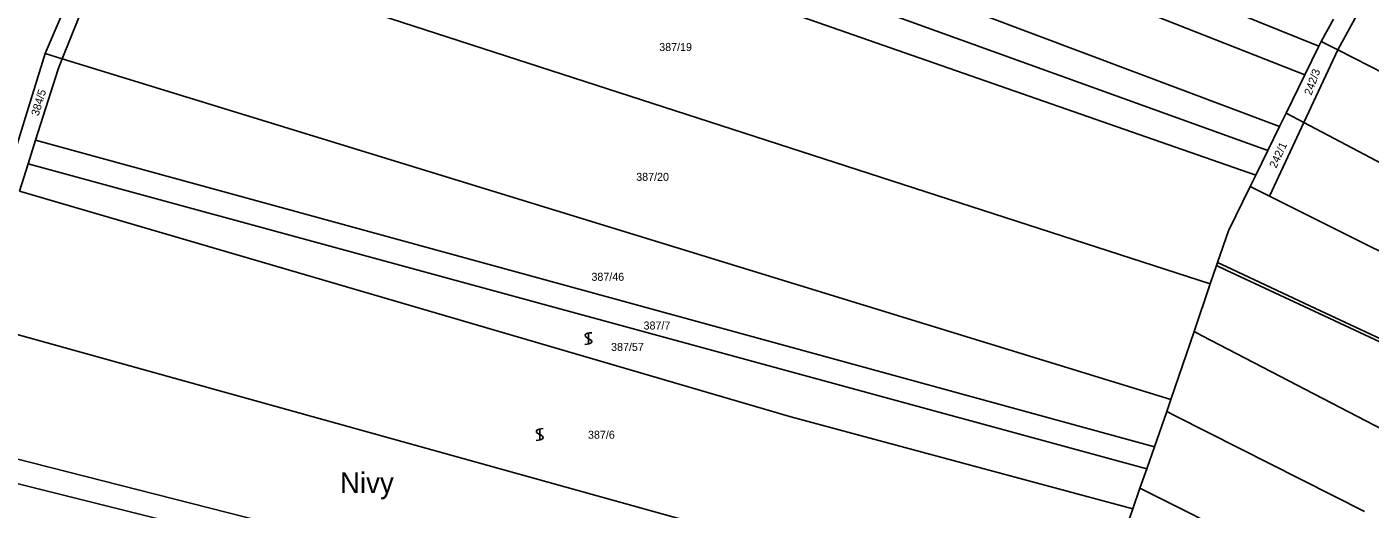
# Model space of a CAD drawing. Extents: x -580630 to -576196, y -1189024 to -1183567.
# Drawn here: x -580125.3 to -579840, y -1186458.9 to -1186356.5 of the extents above; entities that cross this region are included whole.
import ezdxf

# ---------------------------------------------------------------- set-up
doc = ezdxf.new("R2010")
doc.units = 0
for name, color, linetype in [('Vrstva 1', 7, 'Continuous'), ('Vrstva 15', 7, 'Continuous'), ('Vrstva 18', 7, 'Continuous'), ('Vrstva 25', 7, 'Continuous'), ('Vrstva 6', 7, 'Continuous')]:
    doc.layers.add(name, color=color, linetype=linetype)

msp = doc.modelspace()

# ---------------------------------------------------------------- linework, layer by layer
at = {"layer": 'Vrstva 1'}
for p, q in [((-580109.71, -1186334.74), (-580121.44, -1186362.13)), ((-580117.8, -1186363.25), (-580106.79, -1186335.69)), ((-579839.4, -1186347.64), (-579846.88, -1186361.39)), ((-579847.78, -1186354.85), (-579850.43, -1186359.58)), ((-579850.91, -1186360.56), (-579853.89, -1186366.65)), ((-579850.43, -1186359.58), (-579850.91, -1186360.56)), ((-580121.44, -1186362.13), (-580129.43, -1186388.07)), ((-580118.67, -1186365.44), (-580117.8, -1186363.25)), ((-579854.1, -1186376.82), (-579846.88, -1186361.39)), ((-580123.48, -1186380.56), (-580118.67, -1186365.44)), ((-579853.89, -1186366.65), (-579857.89, -1186374.82)), ((-579857.89, -1186374.82), (-579859.26, -1186377.63)), ((-579859.26, -1186377.63), (-579861.75, -1186382.72)), ((-579861.41, -1186392.44), (-579854.1, -1186376.82)), ((-580125.08, -1186385.6), (-580123.48, -1186380.56)), ((-579885.83, -1186445.67), (-580123.48, -1186380.56)), ((-579861.75, -1186382.72), (-579864.31, -1186387.96)), ((-580126.92, -1186391.37), (-580125.08, -1186385.6)), ((-579887.47, -1186450.37), (-580125.08, -1186385.6)), ((-579864.31, -1186387.96), (-579865.5, -1186390.4)), ((-579870.14, -1186399.82), (-579865.5, -1186390.4)), ((-579862.82, -1186391.74), (-579865.5, -1186390.4)), ((-579861.41, -1186392.44), (-579862.82, -1186391.74)), ((-579844.26, -1186401), (-579861.41, -1186392.44)), ((-579872.44, -1186406.57), (-579870.14, -1186399.82)), ((-579808.31, -1186418.94), (-579844.26, -1186401)), ((-579872.44, -1186406.57), (-579872.65, -1186407.2)), ((-579870.48, -1186407.48), (-579872.44, -1186406.57)), ((-579872.65, -1186407.2), (-579873.97, -1186411.08)), ((-579872.65, -1186407.2), (-579870.77, -1186408.08)), ((-579870.77, -1186408.08), (-579851.95, -1186416.9)), ((-579851.66, -1186416.29), (-579870.48, -1186407.48)), ((-579873.97, -1186411.08), (-579877.41, -1186421.18)), ((-579851.95, -1186416.9), (-579815.57, -1186433.93)), ((-579815.26, -1186433.34), (-579851.66, -1186416.29)), ((-579877.41, -1186421.18), (-579882.36, -1186435.66)), ((-579875.68, -1186422.09), (-579877.41, -1186421.18)), ((-579814.2, -1186454.11), (-579875.68, -1186422.09)), ((-579883.23, -1186438.22), (-579885.83, -1186445.67)), ((-579882.36, -1186435.66), (-579883.23, -1186438.22)), ((-579883.23, -1186438.22), (-579881.29, -1186439.2)), ((-579881.29, -1186439.2), (-579841.24, -1186459.45)), ((-579901.91, -1186505.64), (-580142.91, -1186444.32)), ((-579885.83, -1186445.67), (-579887.47, -1186450.37)), ((-580144.29, -1186449.29), (-579902.56, -1186509.53)), ((-579887.47, -1186450.37), (-579888.92, -1186454.5)), ((-579888.92, -1186454.5), (-579890.46, -1186458.89)), ((-579886.67, -1186455.62), (-579888.92, -1186454.5)), ((-579860.08, -1186468.9), (-579886.67, -1186455.62)), ((-579890.46, -1186458.89), (-579895.08, -1186472.04))]:
    msp.add_line(p, q, dxfattribs=at)
at = {"layer": 'Vrstva 25'}
for points in [[(-580005.31, -1186421.45), (-580005.82, -1186421.51), (-580006.17, -1186421.56), (-580006.41, -1186421.64), (-580006.59, -1186421.75), (-580006.71, -1186421.84), (-580006.76, -1186422.01), (-580006.71, -1186422.24), (-580006.32, -1186422.56), (-580005.76, -1186422.87), (-580005.41, -1186423.14), (-580005.34, -1186423.34), (-580005.41, -1186423.54), (-580005.57, -1186423.67), (-580005.76, -1186423.74), (-580006.29, -1186423.87), (-580006.81, -1186423.94)], [(-580006.06, -1186423.95), (-580006.06, -1186422.68), (-580006.06, -1186421.45)], [(-580015.66, -1186441.83), (-580016.17, -1186441.89), (-580016.52, -1186441.94), (-580016.76, -1186442.02), (-580016.94, -1186442.13), (-580017.06, -1186442.22), (-580017.11, -1186442.39), (-580017.06, -1186442.62), (-580016.67, -1186442.94), (-580016.11, -1186443.25), (-580015.76, -1186443.52), (-580015.69, -1186443.72), (-580015.76, -1186443.92), (-580015.92, -1186444.05), (-580016.11, -1186444.12), (-580016.64, -1186444.25), (-580017.16, -1186444.32)], [(-580016.41, -1186444.33), (-580016.41, -1186443.06), (-580016.41, -1186441.83)]]:
    msp.add_lwpolyline(points, dxfattribs=at)
at = {"layer": 'Vrstva 6'}
for p, q in [((-579978.67, -1186309.05), (-579850.91, -1186360.56)), ((-580024.29, -1186315.56), (-579859.26, -1186377.63)), ((-580034.68, -1186320.39), (-579861.75, -1186382.72)), ((-579873.97, -1186411.08), (-580106.79, -1186335.69)), ((-579977.84, -1186348.37), (-579864.31, -1186387.96)), ((-579903.23, -1186347.25), (-579853.89, -1186366.65)), ((-579846.88, -1186361.39), (-579850.43, -1186359.58)), ((-580121.44, -1186362.13), (-580117.8, -1186363.25)), ((-580117.8, -1186363.25), (-579882.36, -1186435.66)), ((-579788, -1186391.47), (-579846.88, -1186361.39)), ((-579857.89, -1186374.82), (-579854.1, -1186376.82)), ((-579854.1, -1186376.82), (-579796.41, -1186407.35)), ((-580126.92, -1186391.37), (-579963.05, -1186439.33)), ((-580135.6, -1186419.53), (-579955.05, -1186469.75)), ((-579963.05, -1186439.33), (-579890.46, -1186458.89))]:
    msp.add_line(p, q, dxfattribs=at)

# ---------------------------------------------------------------- texts
at = {"layer": 'Vrstva 15'}
msp.add_text('Nivy', height=4.4, dxfattribs=at).set_placement((-580058.827, -1186455.54))
at = {"layer": 'Vrstva 18'}
for s, p in [('387/19', (-579991.018, -1186361.62)), ('387/20', (-579995.906, -1186389.2)), ('387/46', (-580005.416, -1186410.43)), ('387/7', (-579994.347, -1186420.78)), ('387/57', (-580001.243, -1186425.33)), ('387/6', (-580006.147, -1186443.98))]:
    msp.add_text(s, height=1.7, dxfattribs=at).set_placement(p)
for s, rotation, p in [('242/3', 70.35922, (-579852.503, -1186371.154)), ('384/5', 73.16671, (-580122.841, -1186375.53)), ('242/1', 65.37448, (-579859.987, -1186386.648))]:
    msp.add_text(s, height=1.7, rotation=rotation, dxfattribs=at).set_placement(p)

doc.saveas('drawing.dxf')
